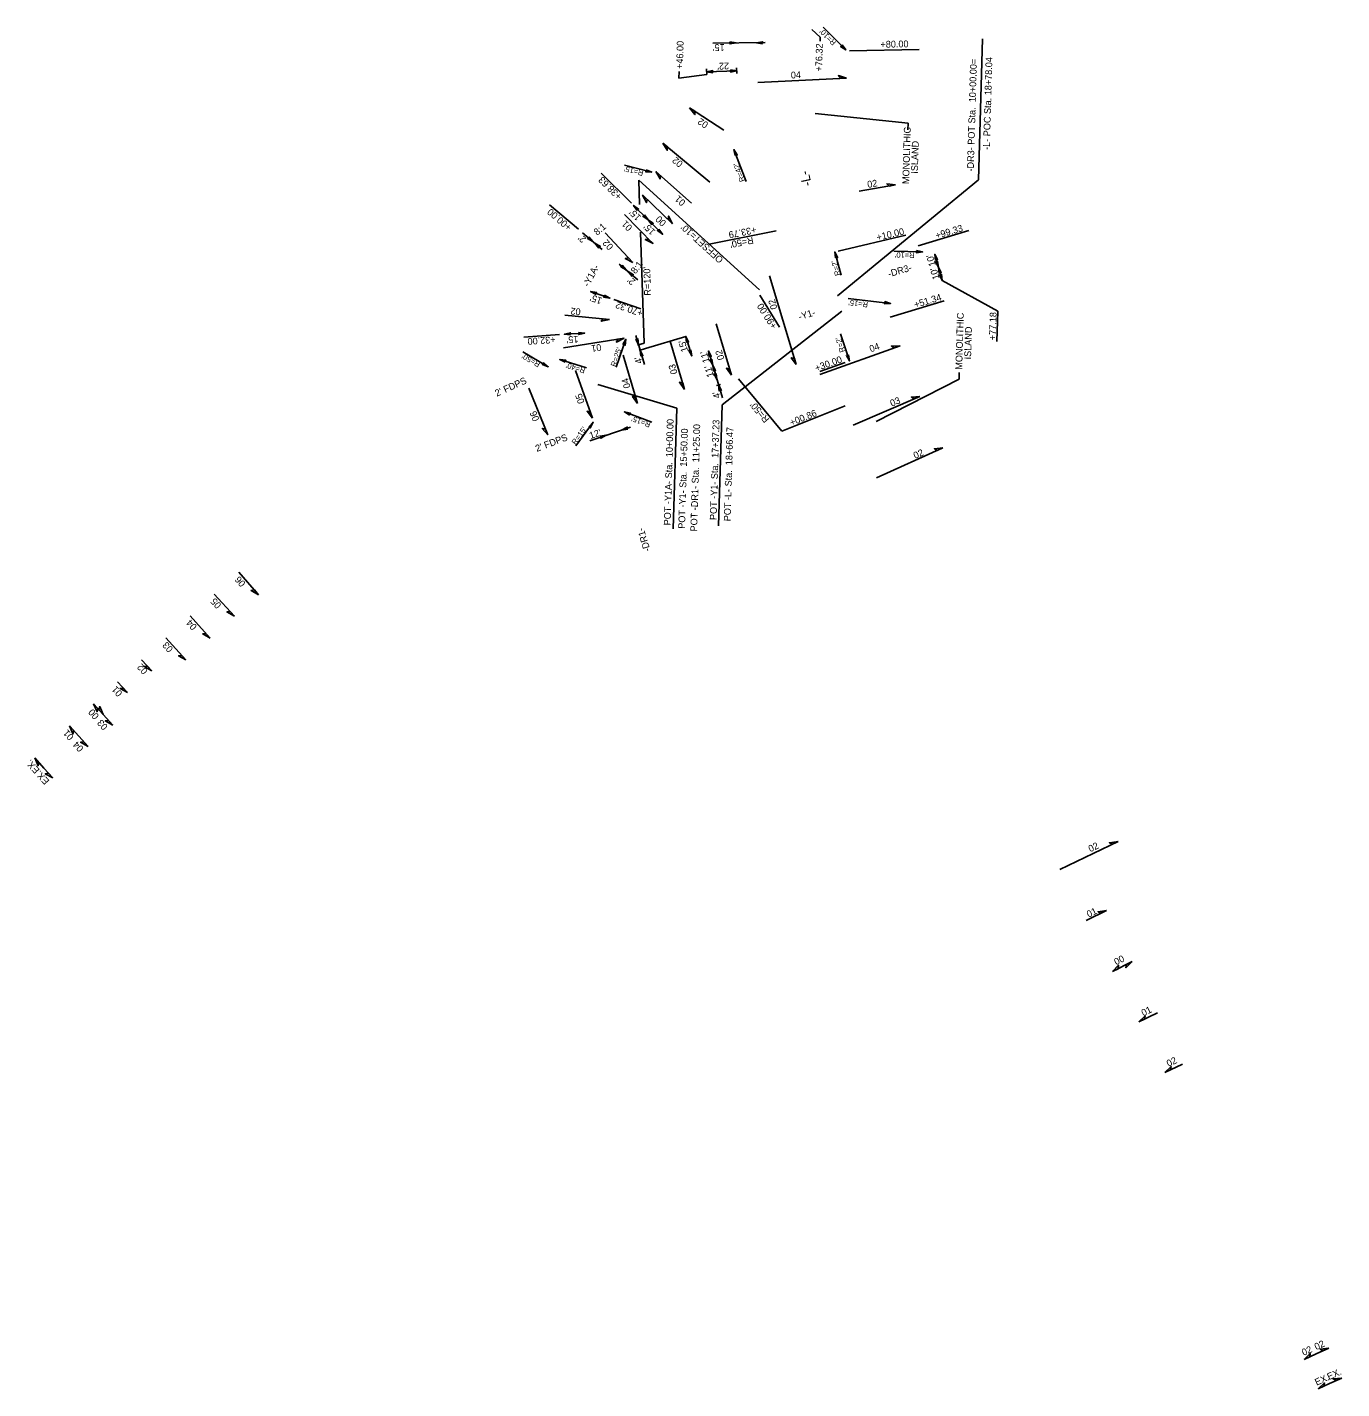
# Model space of a CAD drawing. Extents: x 2096941 to 2098098, y 685096 to 689626.
# Drawn here: x 2097131 to 2098098, y 685096 to 686097 of the extents above; entities that cross this region are included whole.
import ezdxf

# ---------------------------------------------------------------- set-up
doc = ezdxf.new("R2010")
doc.units = 0
for name, color, linetype in [('Prop Dimension', 7, 'Continuous'), ('Prop Dimension Text', 7, 'Continuous'), ('Prop Horizontal Alignment Direction Label', 7, 'Continuous'), ('Prop Horizontal Alignment Station Label', 7, 'Continuous'), ('Prop Superelevation  Arrow CELL', 7, 'Continuous'), ('Prop Superelevation Label', 7, 'Continuous'), ('Prop Terminator CELL', 7, 'Continuous')]:
    doc.layers.add(name, color=color, linetype=linetype)

msp = doc.modelspace()

# ---------------------------------------------------------------- linework, layer by layer
at = {"layer": 'Prop Dimension'}
for p, q in [((2097708.1, 686095.4), (2097714.3, 686089.8)), ((2097716.5, 686097.1), (2097733, 686080.4)), ((2097635.3, 686085.4), (2097673.7, 686085.8)), ((2097714.3, 686089.8), (2097714.3, 686086.9)), ((2097735.8, 686079.8), (2097787.1, 686080.8)), ((2097610.6, 686064.7), (2097610.4, 686059.8)), ((2097630.8, 686066.5), (2097630.9, 686062.4)), ((2097652.9, 686065.1), (2097630.8, 686064.3)), ((2097652.8, 686067.3), (2097653, 686063.2)), ((2097630.9, 686062.3), (2097610.4, 686059.8)), ((2097710.6, 686033.7), (2097778.8, 686026.7)), ((2097778.8, 686026.7), (2097778.6, 686021.7)), ((2097659.8, 685983.8), (2097650.9, 686007.2)), ((2097570.4, 685995.8), (2097590.5, 685990.6)), ((2097575.5, 685967.7), (2097553.2, 685989.8)), ((2097581, 685984.8), (2097669.7, 685904)), ((2097581, 685984.8), (2097581.5, 685966.9)), ((2097536.5, 685948.6), (2097515.4, 685966.6)), ((2097577.1, 685966.2), (2097587.7, 685955.6)), ((2097587.7, 685955.6), (2097598.4, 685945)), ((2097553.9, 685933.8), (2097539.6, 685946)), ((2097582.2, 685946.4), (2097584.8, 685864.8)), ((2097681.8, 685947.4), (2097632.7, 685937.6)), ((2097727.5, 685932.6), (2097777.2, 685944.2)), ((2097823.4, 685947.6), (2097786.3, 685936.4)), ((2097729.6, 685914.8), (2097725, 685932)), ((2097788.9, 685932), (2097768.5, 685932.6)), ((2097801.1, 685920.7), (2097798.4, 685930.3)), ((2097580.3, 685911.4), (2097566.6, 685923)), ((2097803.9, 685911), (2097801.1, 685920.7)), ((2097844.8, 685888.5), (2097803.9, 685911)), ((2097545.5, 685902.9), (2097559.7, 685898)), ((2097582.4, 685890.1), (2097562.5, 685897)), ((2097684.4, 685876.6), (2097670, 685900.2)), ((2097734.9, 685897.8), (2097766, 685894.1)), ((2097805.3, 685896), (2097765.8, 685884.1)), ((2097844.8, 685888.5), (2097844.2, 685866.1)), ((2097522.7, 685871.2), (2097496.4, 685869.4)), ((2097526.2, 685871.5), (2097541.2, 685872.3)), ((2097564.4, 685847.2), (2097571.5, 685867.8)), ((2097578.7, 685870.6), (2097585.1, 685849.3)), ((2097580, 685863.4), (2097584.8, 685864.8)), ((2097585.8, 685861), (2097615.5, 685869.8)), ((2097615.5, 685869.8), (2097619.8, 685855.5)), ((2097729.1, 685871.8), (2097735.7, 685851.8)), ((2097495.7, 685858.5), (2097514.4, 685847.6)), ((2097581.2, 685859.6), (2097585.8, 685861)), ((2097635.3, 685848.6), (2097632.1, 685859.2)), ((2097542.5, 685846.7), (2097522.8, 685852.8)), ((2097635.3, 685848.6), (2097642.5, 685824.6)), ((2097732.7, 685850.7), (2097714, 685844.1)), ((2097640.9, 685834.6), (2097638, 685833.8)), ((2097686.1, 685800.2), (2097654.2, 685838.6)), ((2097755.5, 685807.3), (2097816.3, 685838.4)), ((2097816.5, 685843.4), (2097816.3, 685838.4)), ((2097590.5, 685806.8), (2097570.3, 685814.3)), ((2097732.5, 685818.8), (2097686.1, 685800.2)), ((2097534.6, 685789.3), (2097547.4, 685806.7)), ((2097574.8, 685803.1), (2097545, 685793.2))]:
    msp.add_line(p, q, dxfattribs=at)
at = {"layer": 'Prop Horizontal Alignment Station Label'}
for p, q in [((2097830.5, 685985), (2097833.5, 686088.6)), ((2097726.9, 685899.6), (2097830.5, 685985)), ((2097730.1, 685888.5), (2097642.1, 685819.5)), ((2097550.8, 685834.5), (2097608.9, 685817.1)), ((2097606.3, 685728.5), (2097608.9, 685817.1)), ((2097642.1, 685819.5), (2097639.6, 685730.7))]:
    msp.add_line(p, q, dxfattribs=at)
at = {"layer": 'Prop Superelevation  Arrow CELL'}
for p, q in [((2097668.3, 686056.6), (2097733.7, 686059.8)), ((2097643.4, 686021.5), (2097618.3, 686037.9)), ((2097633.1, 685983.3), (2097598.5, 686012)), ((2097619.7, 685967.7), (2097593.4, 685991.1)), ((2097742.9, 685976.6), (2097769.5, 685981.2)), ((2097605.8, 685952.6), (2097583.7, 685973.8)), ((2097591.4, 685938), (2097570.4, 685959.5)), ((2097576.6, 685924.1), (2097556.1, 685946)), ((2097696.6, 685849.1), (2097677.1, 685914.5)), ((2097559.4, 685882.4), (2097526.5, 685885.5)), ((2097649, 685841.3), (2097637.7, 685879)), ((2097570.1, 685868.6), (2097525.5, 685861.5)), ((2097614.5, 685830.9), (2097603.9, 685866.4)), ((2097580, 685820.6), (2097569.4, 685856.1)), ((2097713.9, 685841.8), (2097773, 685863)), ((2097546.8, 685809.8), (2097534.5, 685844.7)), ((2097514.1, 685797.4), (2097500.2, 685831.7)), ((2097738.4, 685804.7), (2097787.6, 685825.7)), ((2097755.7, 685765.9), (2097804.5, 685787.9)), ((2097301.4, 685680), (2097287, 685696.6)), ((2097283.7, 685664.2), (2097268.9, 685680.5)), ((2097265.9, 685648.1), (2097251.1, 685664.4)), ((2097248.1, 685632), (2097233.3, 685648.3)), ((2097222.9, 685624.1), (2097215.5, 685632.2)), ((2097205.1, 685608), (2097197.8, 685616)), ((2097187.2, 685591.9), (2097180.2, 685599.8)), ((2097194.3, 685584.1), (2097187.2, 685591.9)), ((2097169.4, 685575.9), (2097162.5, 685583.5)), ((2097176.1, 685568.4), (2097169.4, 685575.9)), ((2097143.6, 685552.6), (2097136.9, 685560)), ((2097150.1, 685545.3), (2097143.6, 685552.6)), ((2097890.5, 685478), (2097933.2, 685498.5)), ((2097909.7, 685440.4), (2097924.8, 685447.9)), ((2097929.2, 685403.1), (2097943.5, 685410.3)), ((2097948.5, 685365.9), (2097962.2, 685372.6)), ((2097967.6, 685328.7), (2097980.6, 685334.9)), ((2098078.7, 685122), (2098088, 685126.2)), ((2098069.9, 685117.9), (2098078.7, 685122)), ((2098088.7, 685100.1), (2098097.6, 685104.2)), ((2098080.3, 685096.3), (2098088.7, 685100.1))]:
    msp.add_line(p, q, dxfattribs=at)
for points in [[(2097733.7, 686059.8), (2097727.6, 686061.6), (2097729.1, 686059.6)], [(2097618.3, 686037.9), (2097622.2, 686032.9), (2097622.1, 686035.3)], [(2097598.5, 686012), (2097601.8, 686006.7), (2097602, 686009.1)], [(2097593.4, 685991.1), (2097596.6, 685985.6), (2097596.9, 685988)], [(2097769.5, 685981.2), (2097763.3, 685982.1), (2097765, 685980.4)], [(2097583.7, 685973.7), (2097586.7, 685968.2), (2097587.1, 685970.5)], [(2097605.8, 685952.7), (2097602.8, 685958.3), (2097602.4, 685955.9)], [(2097591.4, 685938.1), (2097585.7, 685941), (2097588.1, 685941.4)], [(2097576.6, 685924.1), (2097571, 685927.1), (2097573.4, 685927.5)], [(2097559.4, 685882.4), (2097553.3, 685881), (2097554.8, 685882.8)], [(2097570.1, 685868.6), (2097564.5, 685865.7), (2097565.5, 685867.9)], [(2097696.6, 685849.1), (2097693, 685854.2), (2097695.3, 685853.5)], [(2097773, 685863), (2097766.6, 685862.8), (2097768.6, 685861.4)], [(2097649, 685841.3), (2097645.3, 685846.4), (2097647.6, 685845.7)], [(2097614.5, 685830.9), (2097610.8, 685836.1), (2097613.2, 685835.4)], [(2097580, 685820.6), (2097576.4, 685825.8), (2097578.7, 685825)], [(2097787.6, 685825.7), (2097781.3, 685825.2), (2097783.3, 685823.9)], [(2097546.8, 685809.8), (2097542.9, 685814.8), (2097545.2, 685814.2)], [(2097514.1, 685797.4), (2097510, 685802.2), (2097512.3, 685801.7)], [(2097804.5, 685787.9), (2097798.2, 685787.3), (2097800.2, 685786)], [(2097301.4, 685680), (2097296, 685683.2), (2097298.4, 685683.5)], [(2097283.7, 685664.2), (2097278.2, 685667.3), (2097280.6, 685667.6)], [(2097265.9, 685648.1), (2097260.4, 685651.2), (2097262.8, 685651.5)], [(2097248.1, 685632), (2097242.6, 685635.1), (2097245, 685635.4)], [(2097222.9, 685624.1), (2097217.4, 685627.2), (2097219.8, 685627.5)], [(2097205.1, 685608), (2097199.6, 685611.1), (2097202, 685611.4)], [(2097180.2, 685599.8), (2097182.7, 685594), (2097183.3, 685596.3)], [(2097187.2, 685591.9), (2097184.7, 685597.7), (2097184.1, 685595.4)], [(2097194.3, 685584.1), (2097188.8, 685587.2), (2097191.2, 685587.6)], [(2097162.5, 685583.5), (2097165, 685577.7), (2097165.6, 685580.1)], [(2097176.1, 685568.4), (2097170.6, 685571.5), (2097173, 685571.8)], [(2097136.9, 685560), (2097139.4, 685554.2), (2097140, 685556.6)], [(2097150.1, 685545.3), (2097144.6, 685548.4), (2097147, 685548.7)], [(2097933.2, 685498.5), (2097926.9, 685497.7), (2097929, 685496.5)], [(2097924.8, 685447.9), (2097918.5, 685447), (2097920.6, 685445.8)], [(2097929.2, 685403.1), (2097933.6, 685407.6), (2097933.3, 685405.1)], [(2097943.5, 685410.3), (2097939, 685405.8), (2097939.4, 685408.2)], [(2097948.5, 685365.9), (2097953.1, 685370.4), (2097952.7, 685368)], [(2097967.6, 685328.7), (2097972.2, 685333.1), (2097971.8, 685330.7)], [(2098088, 685126.2), (2098081.7, 685125.5), (2098083.8, 685124.3)], [(2098069.9, 685117.9), (2098074.5, 685122.2), (2098074.1, 685119.8)], [(2098097.6, 685104.2), (2098091.3, 685103.6), (2098093.4, 685102.3)], [(2098080.3, 685096.3), (2098084.9, 685100.6), (2098084.5, 685098.2)]]:
    msp.add_lwpolyline(points, close=True, dxfattribs=at)
at = {"layer": 'Prop Terminator CELL'}
for points in [[(2097647.9, 686086.3), (2097652.4, 686085.6), (2097647.9, 686084.8), (2097648.4, 686085.6)], [(2097671.9, 686085), (2097667.4, 686085.7), (2097671.9, 686086.5), (2097671.3, 686085.7)], [(2097730.4, 686084.1), (2097733, 686080.4), (2097729.2, 686083), (2097730.2, 686083.2)], [(2097635.4, 686063.7), (2097630.8, 686064.3), (2097635.3, 686065.3), (2097634.8, 686064.5)], [(2097648.4, 686065.8), (2097652.9, 686065.1), (2097648.4, 686064.2), (2097648.9, 686065)], [(2097651.8, 686002.8), (2097650.9, 686007.2), (2097653.3, 686003.3), (2097652.3, 686003.5)], [(2097586.3, 685992.4), (2097590.5, 685990.6), (2097585.9, 685990.9), (2097586.6, 685991.6)], [(2097579.7, 685962.4), (2097577.1, 685966.2), (2097580.8, 685963.5), (2097579.9, 685963.4)], [(2097585.1, 685959.3), (2097587.7, 685955.6), (2097584, 685958.2), (2097584.9, 685958.3)], [(2097590.4, 685951.9), (2097587.7, 685955.6), (2097591.5, 685953), (2097590.5, 685952.8)], [(2097595.7, 685948.7), (2097598.4, 685945), (2097594.6, 685947.6), (2097595.6, 685947.8)], [(2097544.3, 685943), (2097547.2, 685939.5), (2097543.3, 685941.8), (2097544.2, 685942.1)], [(2097551.6, 685934.8), (2097548.7, 685938.3), (2097552.7, 685936), (2097551.7, 685935.7)], [(2097725.4, 685927.5), (2097725, 685932), (2097727, 685927.8), (2097726.1, 685928.2)], [(2097785.1, 685932.9), (2097789.5, 685932), (2097785, 685931.3), (2097785.6, 685932.1)], [(2097798.9, 685925.7), (2097798.4, 685930.3), (2097800.4, 685926.1), (2097799.5, 685926.5)], [(2097800.6, 685925.2), (2097801.1, 685920.7), (2097799.1, 685924.8), (2097800.1, 685924.5)], [(2097568.7, 685922.3), (2097571.6, 685918.8), (2097567.6, 685921.1), (2097568.6, 685921.3)], [(2097576, 685914), (2097573.1, 685917.5), (2097577, 685915.2), (2097576.1, 685915)], [(2097801.6, 685916.1), (2097801.1, 685920.7), (2097803.1, 685916.5), (2097802.2, 685916.9)], [(2097803.4, 685915.6), (2097803.9, 685911), (2097801.9, 685915.2), (2097802.8, 685914.8)], [(2097549.5, 685900.7), (2097545.5, 685902.9), (2097550, 685902.2), (2097549.2, 685901.6)], [(2097555.7, 685900.2), (2097559.7, 685898), (2097555.1, 685898.7), (2097555.9, 685899.3)], [(2097761.7, 685895.4), (2097766, 685894.1), (2097761.5, 685893.8), (2097762.1, 685894.5)], [(2097530.8, 685870.9), (2097526.2, 685871.5), (2097530.7, 685872.5), (2097530.2, 685871.7)], [(2097536.7, 685872.8), (2097541.2, 685872.3), (2097536.8, 685871.2), (2097537.3, 685872.1)], [(2097569.3, 685863.8), (2097571.5, 685867.8), (2097570.8, 685863.2), (2097570.2, 685864)], [(2097580.3, 685868.2), (2097580.8, 685863.6), (2097578.8, 685867.7), (2097579.7, 685867.4)], [(2097616, 685865.3), (2097615.5, 685869.8), (2097617.5, 685865.7), (2097616.6, 685866.1)], [(2097582.5, 685855.3), (2097582, 685859.8), (2097584, 685855.7), (2097583.1, 685856)], [(2097619.2, 685860), (2097619.8, 685855.5), (2097617.7, 685859.6), (2097618.6, 685859.3)], [(2097632.7, 685854.6), (2097632.1, 685859.2), (2097634.2, 685855.1), (2097633.2, 685855.4)], [(2097735, 685856.3), (2097735.7, 685851.8), (2097733.5, 685855.9), (2097734.4, 685855.6)], [(2097510.9, 685850.6), (2097514.4, 685847.6), (2097510.1, 685849.2), (2097511, 685849.6)], [(2097526.8, 685850.8), (2097522.8, 685852.8), (2097527.3, 685852.3), (2097526.5, 685851.7)], [(2097634.7, 685853.2), (2097635.3, 685848.6), (2097633.2, 685852.7), (2097634.1, 685852.4)], [(2097635.8, 685844.1), (2097635.3, 685848.6), (2097637.3, 685844.5), (2097636.4, 685844.8)], [(2097637.9, 685842.6), (2097638.4, 685838.1), (2097636.3, 685842.2), (2097637.3, 685841.9)], [(2097640.1, 685829.7), (2097639.6, 685834.3), (2097641.6, 685830.2), (2097640.7, 685830.5)], [(2097574.2, 685812), (2097570.3, 685814.3), (2097574.8, 685813.5), (2097574, 685812.9)], [(2097544.1, 685803.5), (2097547.4, 685806.7), (2097545.3, 685802.6), (2097545, 685803.5)], [(2097552.5, 685796.5), (2097557, 685797.2), (2097552.9, 685795), (2097553.2, 685795.9)], [(2097572.9, 685801.7), (2097568.3, 685801), (2097572.4, 685803.2), (2097572.1, 685802.2)]]:
    msp.add_lwpolyline(points, close=True, dxfattribs=at)

# ---------------------------------------------------------------- texts
at = {"layer": 'Prop Dimension Text'}
for s, height, rotation, p in [("R=10'", 4, 134.5111, (2097726.3, 686086.1)), ('+46.00', 5, 88.3348, (2097613.3, 686066.4)), ("15'", 5, 180.5837, (2097644, 686084.7)), ('+76.32', 5, 88.3348, (2097715.6, 686064.5)), ('+80.00', 5, 1.1489, (2097758.6, 686082)), ("22'", 5, 182.0995, (2097647.2, 686071.2)), ('MONOLITHIC', 5, 88.3348, (2097779.6, 685981.8)), ('ISLAND', 5, 88.3348, (2097786, 685989.4)), ("R=15'", 4, 165.4509, (2097584.7, 685991.6)), ("R=42'", 4, 110.6431, (2097659.1, 685984.3)), ('+38.63', 5, 135.2721, (2097568.9, 685973.3)), ('+00.00', 5, 139.6194, (2097532, 685950.9)), ("15'", 5, 135.2721, (2097583, 685957.8)), ('8:1', 5, 40.108, (2097550.3, 685943.8)), ("15'", 5, 135.2721, (2097593.6, 685947.3)), ("OFFSET=10'", 5, 137.6599, (2097643.5, 685926.8)), ('+33.79', 5, 191.2625, (2097666.8, 685950.8)), ('+10.00', 5, 13.169, (2097756.3, 685940.1)), ('+99.33', 5, 16.775, (2097799.8, 685941.4)), ("2'", 5, 139.6194, (2097542.7, 685941.9)), ("R=50'", 5, 191.2625, (2097664.7, 685943.1)), ('8:1', 5, 52.1863, (2097578.5, 685915.4)), ("R=2'", 4, 104.8851, (2097729.2, 685915)), ("R=10'", 4, 178.3387, (2097783.7, 685931.4)), ("10'", 5, 105.8349, (2097799.3, 685922.1)), ("R=120'", 5, 91.822, (2097589.9, 685899.9)), ("10'", 5, 105.8349, (2097802, 685912.4)), ("2'", 5, 139.6194, (2097578.9, 685910.9)), ("15'", 5, 160.8753, (2097554.4, 685898)), ('+70.32', 5, 160.8198, (2097584.4, 685888.9)), ("R=15'", 4, 173.1971, (2097749.6, 685895.1)), ('+51.34', 5, 16.775, (2097784.1, 685890.6)), ('+90.00', 5, 122.6986, (2097682.8, 685877.4)), ('MONOLITHIC', 5, 88.3348, (2097818.6, 685845.3)), ('+77.18', 5, 88.3348, (2097843.3, 685867)), ('ISLAND', 5, 88.3348, (2097825.1, 685852.9)), ('+32.00', 5, 183.8205, (2097519.6, 685870)), ("15'", 5, 183.1561, (2097536.4, 685870.3)), ("15'", 5, 106.6572, (2097617.2, 685859.2)), ("R=2'", 4, 108.2223, (2097732.7, 685858.8)), ("R=50'", 4, 149.9663, (2097508.9, 685850.4)), ("R=25'", 4, 70.9351, (2097563.9, 685847.2)), ("11'", 5, 106.6572, (2097633.1, 685851.2)), ('+30.00', 5, 19.5797, (2097711.4, 685844)), ("R=40'", 4, 162.8213, (2097541.9, 685846.4)), ("4'", 5, 106.6572, (2097583.7, 685850.6)), ("11'", 5, 106.6572, (2097636.2, 685840.6)), ("2' FDPS", 5, 24.1455, (2097476.5, 685825.5)), ("4'", 5, 106.6572, (2097641.1, 685825.1)), ("R=50'", 5, 129.7311, (2097677.2, 685809)), ('+00.86', 5, 21.9147, (2097693.1, 685803.9)), ("R=15'", 4, 159.734, (2097590, 685806.5)), ("2' FDPS", 5, 20.8047, (2097506, 685784.9)), ("R=15'", 4, 53.7403, (2097534.4, 685789.9)), ("12'", 5, 18.4646, (2097545.5, 685794.4))]:
    msp.add_text(s, height=height, rotation=rotation, dxfattribs=at).set_placement(p)
at = {"layer": 'Prop Horizontal Alignment Direction Label'}
for s, height, rotation, p in [('-L-', 7, 102.2606, (2097708.1, 685981)), ('-Y1A-', 5, 61.998, (2097544, 685905.9)), ('-DR3-', 5, 16.3375, (2097764.9, 685913.3)), ('-Y1-', 5, 16.6572, (2097699.1, 685881.8)), ('-DR1-', 5, 106.9125, (2097589.6, 685712.5))]:
    msp.add_text(s, height=height, rotation=rotation, dxfattribs=at).set_placement(p)
at = {"layer": 'Prop Horizontal Alignment Station Label'}
for s, p in [('-L- POC Sta. 18+78.04', (2097838.9, 686006.9)), ('-DR3- POT Sta.  10+00.00=', (2097827.1, 685991)), ('POT -Y1A- Sta.  10+00.00', (2097604.3, 685730.9)), ('POT -DR1- Sta.  11+25.00', (2097623.8, 685726.4)), ('POT -Y1- Sta.  17+37.23', (2097638.1, 685734.8)), ('POT -Y1- Sta.  15+50.00', (2097614.9, 685728.4)), ('POT -L- Sta.  18+66.47', (2097648.4, 685733.9))]:
    msp.add_text(s, height=5, rotation=88.3348, dxfattribs=at).set_placement(p)
at = {"layer": 'Prop Superelevation Label'}
for s, rotation, p in [('04', 2.7374, (2097692.8, 686059.4)), ('02', 146.8115, (2097632.5, 686026.6)), ('02', 140.2539, (2097613.8, 685997.5)), ('02', 9.8649, (2097749.3, 685979)), ('01', 138.2527, (2097615.7, 685968.9)), ('01', 134.2502, (2097576.6, 685950.2)), ('00', 136.2514, (2097601.5, 685953.8)), ('02', 133.0697, (2097562.6, 685936.1)), ('02', 106.6572, (2097682.9, 685890.5)), ('02', 174.6092, (2097538.4, 685890.3)), ('01', 188.9331, (2097553, 685864.4)), ('04', 20.2149, (2097751.5, 685858.1)), ('02', 106.6572, (2097643.9, 685853.3)), ('03', 106.6572, (2097609.5, 685842.8)), ('04', 106.6572, (2097575, 685832.5)), ('05', 109.3715, (2097541.2, 685821.4)), ('03', 23.0242, (2097766.9, 685818.1)), ('06', 112.0855, (2097508, 685808.7)), ('02', 24.1462, (2097784.1, 685779.7)), ('06', 130.7855, (2097292.2, 685688.4)), ('05', 131.9907, (2097274.4, 685672.5)), ('04', 131.9907, (2097256.5, 685656.7)), ('03', 131.9907, (2097239, 685640.3)), ('02', 131.9907, (2097220.4, 685624.2)), ('01', 131.9907, (2097201.7, 685607.8)), ('00', 131.9907, (2097184.5, 685591)), ('03', 131.9907, (2097191, 685583.2)), ('01', 131.9907, (2097166, 685575.7)), ('04', 131.9907, (2097173.2, 685567.2)), ('EX.', 131.9907, (2097140.9, 685551.3)), ('EX.', 131.9907, (2097148, 685543.2)), ('02', 25.6257, (2097912.8, 685490.6)), ('01', 26.107, (2097911.6, 685442.5)), ('00', 26.5882, (2097931.8, 685407.5)), ('01', 26.1069, (2097951.8, 685370)), ('02', 25.6256, (2097970.3, 685332.8)), ('02', 24.5661, (2098069.6, 685120.4)), ('02', 24.5661, (2098078.9, 685124.6)), ('EX.', 24.5661, (2098079.2, 685098.5)), ('EX.', 24.5661, (2098088.2, 685102.6))]:
    msp.add_text(s, height=5, rotation=rotation, dxfattribs=at).set_placement(p)

doc.saveas('drawing.dxf')
